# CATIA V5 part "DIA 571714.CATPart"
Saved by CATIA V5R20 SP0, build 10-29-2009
Part number: DIA 571714
Revision: ANY
Definition: UNKNOWN
Nomenclature: DIA 571714
Source: Unknown
Bounding box of the stored display mesh (mm): x -2.85 to 2.85, y -7.925 to 9.045, z -2.711 to 2.711
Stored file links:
  C:\Users\Utente\Desktop\IO LAVORO\3D X SITO CF\CUMSA\3D files FA\FA 105712-21\DIA 571714.CATPart
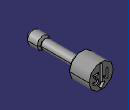
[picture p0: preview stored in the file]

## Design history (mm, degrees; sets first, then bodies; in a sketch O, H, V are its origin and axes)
Body1 "Cortar-Extruir2" (main body)
  Solid1: solid without history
